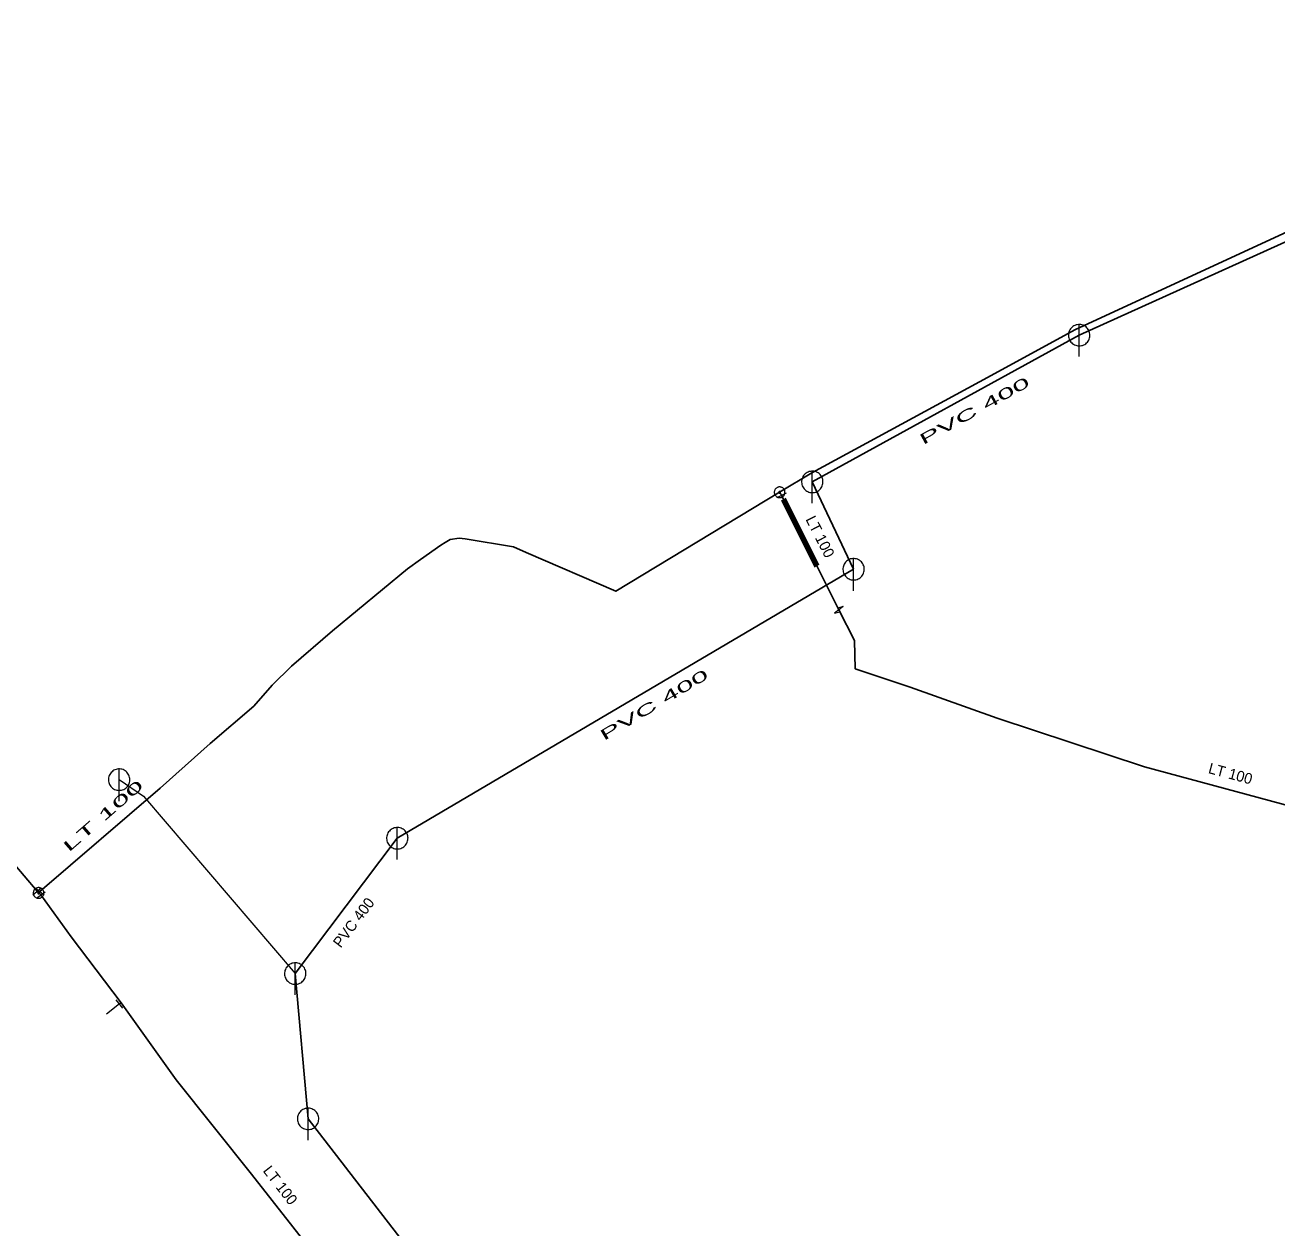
# Model space of a CAD drawing. Extents: x -659250 to -657316, y -997555 to -993684.
# Drawn here: x -658101 to -657984.1, y -996412 to -996299.7 of the extents above; entities that cross this region are included whole.
import ezdxf

# ---------------------------------------------------------------- set-up
doc = ezdxf.new("R2010")
doc.units = 0
doc.header["$LTSCALE"] = 0.4
doc.layers.add('1', color=7, linetype='Continuous')
for name, color, linetype, lineweight in [('11', 7, 'Continuous', 13), ('13', 7, 'Continuous', 13), ('14', 7, 'Continuous', 25), ('17', 7, 'Continuous', 25), ('22', 7, 'Continuous', 13), ('3', 7, 'Continuous', 106), ('34', 7, 'Continuous', 13), ('47', 7, 'Continuous', 13)]:
    doc.layers.add(name, color=color, linetype=linetype, lineweight=lineweight)

msp = doc.modelspace()

# ---------------------------------------------------------------- linework, layer by layer
at = {"layer": '11'}
msp.add_lwpolyline([(-658092.17, -996370.14), (-658089.899, -996371.69), (-658075.73, -996388.25)], dxfattribs=at)
at = {"layer": '13'}
msp.add_line((-658092.133, -996391.09), (-658093.346, -996392.048), dxfattribs=at)
at = {"layer": '14'}
for p, q in [((-657955.859, -996307.48), (-658002.53, -996328.629)), ((-658002.53, -996328.629), (-658027.449, -996342.329)), ((-658027.449, -996342.329), (-658023.59, -996350.489)), ((-658023.59, -996350.489), (-658066.199, -996375.609)), ((-658066.199, -996375.609), (-658075.73, -996388.25)), ((-658075.73, -996388.25), (-658074.53, -996401.82)), ((-658074.53, -996401.82), (-658049.01, -996434.84))]:
    msp.add_line(p, q, dxfattribs=at)
at = {"layer": '14', "lineweight": 13}
for p, q in [((-658030.5, -996343.3), (-658030.32, -996343.6)), ((-658099.695, -996380.723), (-658099.585, -996380.579)), ((-658091.995, -996390.978), (-658092.133, -996391.09))]:
    msp.add_line(p, q, dxfattribs=at)
msp.add_lwpolyline([(-658099.489, -996380.899), (-658099.695, -996380.723), (-658099.838, -996380.568)], dxfattribs=at)
at = {"layer": '17'}
for points in [[(-658099.838, -996380.568), (-658104.721, -996374.813), (-658108.715, -996370.004), (-658114.16, -996363.631), (-658120.304, -996355.87), (-658125.403, -996349.761), (-658132.55, -996341.083), (-658140.008, -996331.868), (-658145.489, -996324.896), (-658149.55, -996319.91), (-658154.151, -996314.079), (-658157.877, -996309.767), (-658163.125, -996303.473), (-658168.581, -996296.64)], [(-658030.5, -996343.3), (-658027.489, -996341.48), (-658011.82, -996332.971), (-658002.858, -996328.082), (-657979.864, -996317.496), (-657954.87, -996306.27), (-657953.079, -996302.94), (-657951.27, -996301.8)], [(-658099.585, -996380.579), (-658088.329, -996370.949), (-658083.68, -996366.75), (-658079.6, -996363.289), (-658077.87, -996361.32), (-658076.09, -996359.55), (-658072.239, -996356.239), (-658065.25, -996350.449), (-658064.02, -996349.579), (-658062.14, -996348.25), (-658061.739, -996348), (-658061.25, -996347.71), (-658060.43, -996347.6), (-658059.859, -996347.649), (-658055.359, -996348.41), (-658054.175, -996348.922), (-658045.8, -996352.55), (-658030.5, -996343.3)], [(-658030.32, -996343.6), (-658029.118, -996345.988), (-658024.976, -996354.29)], [(-658024.976, -996354.29), (-658023.51, -996357.14), (-658023.44, -996359.78), (-658018.309, -996361.489), (-658010.19, -996364.399), (-657996.42, -996368.949), (-657979.379, -996373.55), (-657959.55, -996379.789), (-657941.66, -996385.3), (-657925.98, -996390.19), (-657916.51, -996393.21), (-657908.82, -996396.53)], [(-658055.423, -996446.975), (-658052.642, -996444.888), (-658054.289, -996442.579), (-658058.616, -996436.102), (-658062.973, -996429.688), (-658065.484, -996426.39), (-658068.699, -996421.191), (-658074.013, -996414.35), (-658079.82, -996406.977), (-658086.833, -996398.186), (-658091.995, -996390.978), (-658096.636, -996384.813), (-658099.489, -996380.899)]]:
    msp.add_lwpolyline(points, dxfattribs=at)
at = {"layer": '22'}
for p, q in [((-658002.53, -996330.629), (-658002.529, -996327.629)), ((-658027.449, -996344.329), (-658027.448, -996341.329)), ((-658023.59, -996352.489), (-658023.589, -996349.489)), ((-658092.17, -996372.14), (-658092.169, -996369.14)), ((-658066.199, -996377.609), (-658066.198, -996374.609)), ((-658075.73, -996390.25), (-658075.729, -996387.25)), ((-658074.53, -996403.82), (-658074.529, -996400.82))]:
    msp.add_line(p, q, dxfattribs=at)
for points in [[(-658001.53, -996328.629), (-658001.535, -996328.52), (-658001.553, -996328.412), (-658001.583, -996328.306), (-658001.623, -996328.205), (-658001.675, -996328.108), (-658001.737, -996328.018), (-658001.809, -996327.935), (-658001.889, -996327.861), (-658001.977, -996327.795), (-658002.071, -996327.74), (-658002.171, -996327.695), (-658002.276, -996327.662), (-658002.383, -996327.64), (-658002.492, -996327.63), (-658002.602, -996327.632), (-658002.71, -996327.646), (-658002.817, -996327.671), (-658002.92, -996327.708), (-658003.018, -996327.757), (-658003.11, -996327.815), (-658003.196, -996327.884), (-658003.273, -996327.961), (-658003.342, -996328.047), (-658003.401, -996328.139), (-658003.449, -996328.237), (-658003.486, -996328.34), (-658003.512, -996328.447), (-658003.526, -996328.555), (-658003.529, -996328.665), (-658003.519, -996328.774), (-658003.498, -996328.881), (-658003.464, -996328.985), (-658003.42, -996329.085), (-658003.365, -996329.18), (-658003.299, -996329.268), (-658003.225, -996329.348), (-658003.142, -996329.42), (-658003.052, -996329.482), (-658002.956, -996329.534), (-658002.854, -996329.575), (-658002.749, -996329.605), (-658002.641, -996329.623), (-658002.531, -996329.629), (-658002.422, -996329.623), (-658002.314, -996329.605), (-658002.209, -996329.576), (-658002.107, -996329.535), (-658002.01, -996329.483), (-658001.92, -996329.421), (-658001.837, -996329.35), (-658001.762, -996329.27), (-658001.697, -996329.182), (-658001.641, -996329.088), (-658001.597, -996328.988), (-658001.563, -996328.884), (-658001.541, -996328.776), (-658001.531, -996328.667)], [(-658026.449, -996342.329), (-658026.454, -996342.22), (-658026.472, -996342.112), (-658026.502, -996342.006), (-658026.542, -996341.905), (-658026.594, -996341.808), (-658026.656, -996341.718), (-658026.728, -996341.635), (-658026.808, -996341.561), (-658026.896, -996341.495), (-658026.99, -996341.44), (-658027.09, -996341.395), (-658027.195, -996341.362), (-658027.302, -996341.34), (-658027.411, -996341.33), (-658027.521, -996341.332), (-658027.629, -996341.346), (-658027.736, -996341.371), (-658027.839, -996341.408), (-658027.937, -996341.457), (-658028.029, -996341.515), (-658028.115, -996341.584), (-658028.192, -996341.661), (-658028.261, -996341.747), (-658028.32, -996341.839), (-658028.368, -996341.937), (-658028.405, -996342.04), (-658028.431, -996342.147), (-658028.445, -996342.255), (-658028.448, -996342.365), (-658028.438, -996342.474), (-658028.417, -996342.581), (-658028.383, -996342.685), (-658028.339, -996342.785), (-658028.284, -996342.88), (-658028.218, -996342.968), (-658028.144, -996343.048), (-658028.061, -996343.12), (-658027.971, -996343.182), (-658027.875, -996343.234), (-658027.773, -996343.275), (-658027.668, -996343.305), (-658027.56, -996343.323), (-658027.45, -996343.329), (-658027.341, -996343.323), (-658027.233, -996343.305), (-658027.128, -996343.276), (-658027.026, -996343.235), (-658026.929, -996343.183), (-658026.839, -996343.121), (-658026.756, -996343.05), (-658026.681, -996342.97), (-658026.616, -996342.882), (-658026.56, -996342.788), (-658026.516, -996342.688), (-658026.482, -996342.584), (-658026.46, -996342.476), (-658026.45, -996342.367)], [(-658022.59, -996350.489), (-658022.595, -996350.38), (-658022.613, -996350.272), (-658022.643, -996350.166), (-658022.683, -996350.065), (-658022.735, -996349.968), (-658022.797, -996349.878), (-658022.869, -996349.795), (-658022.949, -996349.721), (-658023.037, -996349.655), (-658023.131, -996349.6), (-658023.231, -996349.555), (-658023.336, -996349.522), (-658023.443, -996349.5), (-658023.552, -996349.49), (-658023.662, -996349.492), (-658023.77, -996349.506), (-658023.877, -996349.531), (-658023.98, -996349.568), (-658024.078, -996349.617), (-658024.17, -996349.675), (-658024.256, -996349.744), (-658024.333, -996349.821), (-658024.402, -996349.907), (-658024.461, -996349.999), (-658024.509, -996350.097), (-658024.546, -996350.2), (-658024.572, -996350.307), (-658024.586, -996350.415), (-658024.589, -996350.525), (-658024.579, -996350.634), (-658024.558, -996350.741), (-658024.524, -996350.845), (-658024.48, -996350.945), (-658024.425, -996351.04), (-658024.359, -996351.128), (-658024.285, -996351.208), (-658024.202, -996351.28), (-658024.112, -996351.342), (-658024.016, -996351.394), (-658023.914, -996351.435), (-658023.809, -996351.465), (-658023.701, -996351.483), (-658023.591, -996351.489), (-658023.482, -996351.483), (-658023.374, -996351.465), (-658023.269, -996351.436), (-658023.167, -996351.395), (-658023.07, -996351.343), (-658022.98, -996351.281), (-658022.897, -996351.21), (-658022.822, -996351.13), (-658022.757, -996351.042), (-658022.701, -996350.948), (-658022.657, -996350.848), (-658022.623, -996350.744), (-658022.601, -996350.636), (-658022.591, -996350.527)], [(-658091.17, -996370.14), (-658091.175, -996370.031), (-658091.193, -996369.923), (-658091.223, -996369.817), (-658091.263, -996369.716), (-658091.315, -996369.619), (-658091.377, -996369.529), (-658091.449, -996369.446), (-658091.529, -996369.372), (-658091.617, -996369.306), (-658091.711, -996369.251), (-658091.811, -996369.206), (-658091.916, -996369.173), (-658092.023, -996369.151), (-658092.132, -996369.141), (-658092.242, -996369.143), (-658092.35, -996369.157), (-658092.457, -996369.182), (-658092.56, -996369.219), (-658092.658, -996369.268), (-658092.75, -996369.326), (-658092.836, -996369.395), (-658092.913, -996369.472), (-658092.982, -996369.558), (-658093.041, -996369.65), (-658093.089, -996369.748), (-658093.126, -996369.851), (-658093.152, -996369.958), (-658093.166, -996370.066), (-658093.169, -996370.176), (-658093.159, -996370.285), (-658093.138, -996370.392), (-658093.104, -996370.496), (-658093.06, -996370.596), (-658093.005, -996370.691), (-658092.939, -996370.779), (-658092.865, -996370.859), (-658092.782, -996370.931), (-658092.692, -996370.993), (-658092.596, -996371.045), (-658092.494, -996371.086), (-658092.389, -996371.116), (-658092.281, -996371.134), (-658092.171, -996371.14), (-658092.062, -996371.134), (-658091.954, -996371.116), (-658091.849, -996371.087), (-658091.747, -996371.046), (-658091.65, -996370.994), (-658091.56, -996370.932), (-658091.477, -996370.861), (-658091.402, -996370.781), (-658091.337, -996370.693), (-658091.281, -996370.599), (-658091.237, -996370.499), (-658091.203, -996370.395), (-658091.181, -996370.287), (-658091.171, -996370.178)], [(-658065.199, -996375.609), (-658065.204, -996375.5), (-658065.222, -996375.392), (-658065.252, -996375.286), (-658065.292, -996375.185), (-658065.344, -996375.088), (-658065.406, -996374.998), (-658065.478, -996374.915), (-658065.558, -996374.841), (-658065.646, -996374.775), (-658065.74, -996374.72), (-658065.84, -996374.675), (-658065.945, -996374.642), (-658066.052, -996374.62), (-658066.161, -996374.61), (-658066.271, -996374.612), (-658066.379, -996374.626), (-658066.486, -996374.651), (-658066.589, -996374.688), (-658066.687, -996374.737), (-658066.779, -996374.795), (-658066.865, -996374.864), (-658066.942, -996374.941), (-658067.011, -996375.027), (-658067.07, -996375.119), (-658067.118, -996375.217), (-658067.155, -996375.32), (-658067.181, -996375.427), (-658067.195, -996375.535), (-658067.198, -996375.645), (-658067.188, -996375.754), (-658067.167, -996375.861), (-658067.133, -996375.965), (-658067.089, -996376.065), (-658067.034, -996376.16), (-658066.968, -996376.248), (-658066.894, -996376.328), (-658066.811, -996376.4), (-658066.721, -996376.462), (-658066.625, -996376.514), (-658066.523, -996376.555), (-658066.418, -996376.585), (-658066.31, -996376.603), (-658066.2, -996376.609), (-658066.091, -996376.603), (-658065.983, -996376.585), (-658065.878, -996376.556), (-658065.776, -996376.515), (-658065.679, -996376.463), (-658065.589, -996376.401), (-658065.506, -996376.33), (-658065.431, -996376.25), (-658065.366, -996376.162), (-658065.31, -996376.068), (-658065.266, -996375.968), (-658065.232, -996375.864), (-658065.21, -996375.756), (-658065.2, -996375.647)], [(-658074.73, -996388.25), (-658074.735, -996388.141), (-658074.753, -996388.033), (-658074.783, -996387.927), (-658074.823, -996387.826), (-658074.875, -996387.729), (-658074.937, -996387.639), (-658075.009, -996387.556), (-658075.089, -996387.482), (-658075.177, -996387.416), (-658075.271, -996387.361), (-658075.371, -996387.316), (-658075.476, -996387.283), (-658075.583, -996387.261), (-658075.692, -996387.251), (-658075.802, -996387.253), (-658075.91, -996387.267), (-658076.017, -996387.292), (-658076.12, -996387.329), (-658076.218, -996387.378), (-658076.31, -996387.436), (-658076.396, -996387.505), (-658076.473, -996387.582), (-658076.542, -996387.668), (-658076.601, -996387.76), (-658076.649, -996387.858), (-658076.686, -996387.961), (-658076.712, -996388.068), (-658076.726, -996388.176), (-658076.729, -996388.286), (-658076.719, -996388.395), (-658076.698, -996388.502), (-658076.664, -996388.606), (-658076.62, -996388.706), (-658076.565, -996388.801), (-658076.499, -996388.889), (-658076.425, -996388.969), (-658076.342, -996389.041), (-658076.252, -996389.103), (-658076.156, -996389.155), (-658076.054, -996389.196), (-658075.949, -996389.226), (-658075.841, -996389.244), (-658075.731, -996389.25), (-658075.622, -996389.244), (-658075.514, -996389.226), (-658075.409, -996389.197), (-658075.307, -996389.156), (-658075.21, -996389.104), (-658075.12, -996389.042), (-658075.037, -996388.971), (-658074.962, -996388.891), (-658074.897, -996388.803), (-658074.841, -996388.709), (-658074.797, -996388.609), (-658074.763, -996388.505), (-658074.741, -996388.397), (-658074.731, -996388.288)], [(-658073.53, -996401.82), (-658073.535, -996401.711), (-658073.553, -996401.603), (-658073.583, -996401.497), (-658073.623, -996401.396), (-658073.675, -996401.299), (-658073.737, -996401.209), (-658073.809, -996401.126), (-658073.889, -996401.052), (-658073.977, -996400.986), (-658074.071, -996400.931), (-658074.171, -996400.886), (-658074.276, -996400.853), (-658074.383, -996400.831), (-658074.492, -996400.821), (-658074.602, -996400.823), (-658074.71, -996400.837), (-658074.817, -996400.862), (-658074.92, -996400.899), (-658075.018, -996400.948), (-658075.11, -996401.006), (-658075.196, -996401.075), (-658075.273, -996401.152), (-658075.342, -996401.238), (-658075.401, -996401.33), (-658075.449, -996401.428), (-658075.486, -996401.531), (-658075.512, -996401.638), (-658075.526, -996401.746), (-658075.529, -996401.856), (-658075.519, -996401.965), (-658075.498, -996402.072), (-658075.464, -996402.176), (-658075.42, -996402.276), (-658075.365, -996402.371), (-658075.299, -996402.459), (-658075.225, -996402.539), (-658075.142, -996402.611), (-658075.052, -996402.673), (-658074.956, -996402.725), (-658074.854, -996402.766), (-658074.749, -996402.796), (-658074.641, -996402.814), (-658074.531, -996402.82), (-658074.422, -996402.814), (-658074.314, -996402.796), (-658074.209, -996402.767), (-658074.107, -996402.726), (-658074.01, -996402.674), (-658073.92, -996402.612), (-658073.837, -996402.541), (-658073.762, -996402.461), (-658073.697, -996402.373), (-658073.641, -996402.279), (-658073.597, -996402.179), (-658073.563, -996402.075), (-658073.541, -996401.967), (-658073.531, -996401.858)]]:
    msp.add_lwpolyline(points, close=True, dxfattribs=at)
at = {"layer": '3'}
msp.add_line((-658030.144, -996343.94), (-658027.023, -996350.187), dxfattribs=at)
at = {"layer": '3', "lineweight": 100}
msp.add_line((-658030.144, -996343.94), (-658027.023, -996350.187), dxfattribs=at)
at = {"layer": '34'}
for p, q in [((-658029.873, -996343.374), (-658030.766, -996343.824)), ((-658100.218, -996380.891), (-658099.456, -996380.244)), ((-658099.983, -996380.277), (-658099.186, -996380.881)), ((-658099.892, -996381.193), (-658099.084, -996380.604)), ((-658091.817, -996391.477), (-658092.447, -996390.701))]:
    msp.add_line(p, q, dxfattribs=at)
at = {"layer": '47'}
msp.add_line((-658024.572, -996353.979), (-658025.065, -996354.11), dxfattribs=at)
for points in [[(-658030.072, -996343.041), (-658030.101, -996342.998), (-658030.135, -996342.958), (-658030.173, -996342.922), (-658030.213, -996342.889), (-658030.258, -996342.862), (-658030.306, -996342.839), (-658030.355, -996342.822), (-658030.406, -996342.809), (-658030.457, -996342.802), (-658030.51, -996342.8), (-658030.562, -996342.803), (-658030.613, -996342.813), (-658030.663, -996342.827), (-658030.712, -996342.847), (-658030.758, -996342.872), (-658030.801, -996342.901), (-658030.841, -996342.935), (-658030.878, -996342.973), (-658030.91, -996343.013), (-658030.937, -996343.058), (-658030.96, -996343.106), (-658030.978, -996343.155), (-658030.991, -996343.206), (-658030.998, -996343.257), (-658030.999, -996343.31), (-658030.996, -996343.362), (-658030.987, -996343.414), (-658030.972, -996343.463), (-658030.952, -996343.512), (-658030.927, -996343.558), (-658030.898, -996343.601), (-658030.864, -996343.641), (-658030.827, -996343.678), (-658030.786, -996343.71), (-658030.741, -996343.737), (-658030.694, -996343.761), (-658030.645, -996343.779), (-658030.594, -996343.791), (-658030.542, -996343.798), (-658030.489, -996343.799), (-658030.437, -996343.796), (-658030.386, -996343.787), (-658030.336, -996343.772), (-658030.287, -996343.752), (-658030.241, -996343.727), (-658030.198, -996343.698), (-658030.158, -996343.664), (-658030.121, -996343.627), (-658030.089, -996343.586), (-658030.062, -996343.541), (-658030.038, -996343.494), (-658030.021, -996343.445), (-658030.009, -996343.394), (-658030.002, -996343.342), (-658030, -996343.289), (-658030.003, -996343.237), (-658030.013, -996343.186), (-658030.027, -996343.136), (-658030.047, -996343.087)], [(-658030.429, -996343.257), (-658030.434, -996343.249), (-658030.44, -996343.244), (-658030.446, -996343.238), (-658030.452, -996343.232), (-658030.46, -996343.228), (-658030.468, -996343.224), (-658030.476, -996343.221), (-658030.484, -996343.219), (-658030.493, -996343.218), (-658030.501, -996343.218), (-658030.51, -996343.218), (-658030.518, -996343.22), (-658030.526, -996343.222), (-658030.534, -996343.225), (-658030.542, -996343.229), (-658030.55, -996343.234), (-658030.555, -996343.24), (-658030.561, -996343.246), (-658030.567, -996343.252), (-658030.571, -996343.26), (-658030.575, -996343.268), (-658030.578, -996343.276), (-658030.58, -996343.284), (-658030.582, -996343.293), (-658030.581, -996343.301), (-658030.581, -996343.31), (-658030.579, -996343.318), (-658030.577, -996343.326), (-658030.574, -996343.334), (-658030.57, -996343.342), (-658030.565, -996343.35), (-658030.559, -996343.355), (-658030.553, -996343.361), (-658030.547, -996343.367), (-658030.539, -996343.371), (-658030.532, -996343.375), (-658030.523, -996343.378), (-658030.515, -996343.38), (-658030.506, -996343.382), (-658030.498, -996343.381), (-658030.489, -996343.381), (-658030.481, -996343.379), (-658030.473, -996343.377), (-658030.465, -996343.374), (-658030.457, -996343.37), (-658030.449, -996343.365), (-658030.444, -996343.359), (-658030.438, -996343.353), (-658030.432, -996343.347), (-658030.428, -996343.339), (-658030.424, -996343.332), (-658030.421, -996343.323), (-658030.419, -996343.315), (-658030.418, -996343.306), (-658030.418, -996343.298), (-658030.418, -996343.289), (-658030.42, -996343.281), (-658030.422, -996343.273), (-658030.425, -996343.265)], [(-658099.195, -996380.723), (-658099.198, -996380.671), (-658099.206, -996380.619), (-658099.22, -996380.569), (-658099.237, -996380.52), (-658099.262, -996380.473), (-658099.291, -996380.429), (-658099.323, -996380.389), (-658099.36, -996380.352), (-658099.401, -996380.319), (-658099.445, -996380.29), (-658099.492, -996380.266), (-658099.541, -996380.248), (-658099.59, -996380.234), (-658099.642, -996380.226), (-658099.695, -996380.223), (-658099.747, -996380.226), (-658099.799, -996380.234), (-658099.85, -996380.248), (-658099.897, -996380.266), (-658099.945, -996380.29), (-658099.989, -996380.319), (-658100.029, -996380.352), (-658100.066, -996380.389), (-658100.1, -996380.429), (-658100.127, -996380.473), (-658100.152, -996380.52), (-658100.171, -996380.569), (-658100.183, -996380.619), (-658100.191, -996380.671), (-658100.195, -996380.723), (-658100.191, -996380.775), (-658100.183, -996380.827), (-658100.171, -996380.878), (-658100.152, -996380.926), (-658100.127, -996380.973), (-658100.1, -996381.017), (-658100.066, -996381.058), (-658100.029, -996381.095), (-658099.989, -996381.128), (-658099.945, -996381.156), (-658099.897, -996381.18), (-658099.85, -996381.199), (-658099.799, -996381.212), (-658099.747, -996381.22), (-658099.695, -996381.223), (-658099.642, -996381.22), (-658099.59, -996381.212), (-658099.541, -996381.199), (-658099.492, -996381.18), (-658099.445, -996381.156), (-658099.401, -996381.128), (-658099.36, -996381.095), (-658099.323, -996381.058), (-658099.291, -996381.017), (-658099.262, -996380.973), (-658099.237, -996380.926), (-658099.22, -996380.878), (-658099.206, -996380.827), (-658099.198, -996380.775)], [(-658099.612, -996380.723), (-658099.612, -996380.714), (-658099.615, -996380.706), (-658099.617, -996380.698), (-658099.62, -996380.69), (-658099.624, -996380.682), (-658099.629, -996380.675), (-658099.634, -996380.668), (-658099.639, -996380.662), (-658099.647, -996380.657), (-658099.654, -996380.652), (-658099.661, -996380.648), (-658099.669, -996380.645), (-658099.678, -996380.643), (-658099.686, -996380.641), (-658099.695, -996380.641), (-658099.703, -996380.641), (-658099.712, -996380.643), (-658099.72, -996380.645), (-658099.728, -996380.648), (-658099.735, -996380.652), (-658099.742, -996380.657), (-658099.75, -996380.662), (-658099.755, -996380.668), (-658099.762, -996380.675), (-658099.766, -996380.682), (-658099.769, -996380.69), (-658099.772, -996380.698), (-658099.774, -996380.706), (-658099.777, -996380.714), (-658099.777, -996380.723), (-658099.777, -996380.732), (-658099.774, -996380.74), (-658099.772, -996380.748), (-658099.769, -996380.756), (-658099.766, -996380.764), (-658099.762, -996380.771), (-658099.755, -996380.778), (-658099.75, -996380.784), (-658099.742, -996380.79), (-658099.735, -996380.794), (-658099.728, -996380.798), (-658099.72, -996380.801), (-658099.712, -996380.803), (-658099.703, -996380.805), (-658099.695, -996380.805), (-658099.686, -996380.805), (-658099.678, -996380.803), (-658099.669, -996380.801), (-658099.661, -996380.798), (-658099.654, -996380.794), (-658099.647, -996380.79), (-658099.639, -996380.784), (-658099.634, -996380.778), (-658099.629, -996380.771), (-658099.624, -996380.764), (-658099.62, -996380.756), (-658099.617, -996380.748), (-658099.615, -996380.74), (-658099.612, -996380.732)]]:
    msp.add_lwpolyline(points, close=True, dxfattribs=at)
msp.add_lwpolyline([(-658024.572, -996353.979), (-658025.379, -996354.6), (-658024.886, -996354.469)], dxfattribs=at)

# ---------------------------------------------------------------- texts
at = {"layer": '1'}
for s, rotation, width, p in [('PVC 400 ', 29, 2.15, (-658017.1, -996338.905)), ('PVC 400 ', 31, 2.15, (-658046.901, -996366.537)), ('LT 100', 41, 2.25, (-658096.877, -996376.965))]:
    msp.add_text(s, height=1, rotation=rotation, dxfattribs=dict(at, width=width)).set_placement(p)
for s, rotation, p in [('LT 100', 297, (-658028.101, -996345.818)), ('LT 100', 345, (-657990.538, -996369.516)), ('PVC 400 ', 53, (-658071.486, -996385.919)), ('LT 100', 308, (-658078.797, -996406.681))]:
    msp.add_text(s, height=1, rotation=rotation, dxfattribs=at).set_placement(p)

doc.saveas('drawing.dxf')
